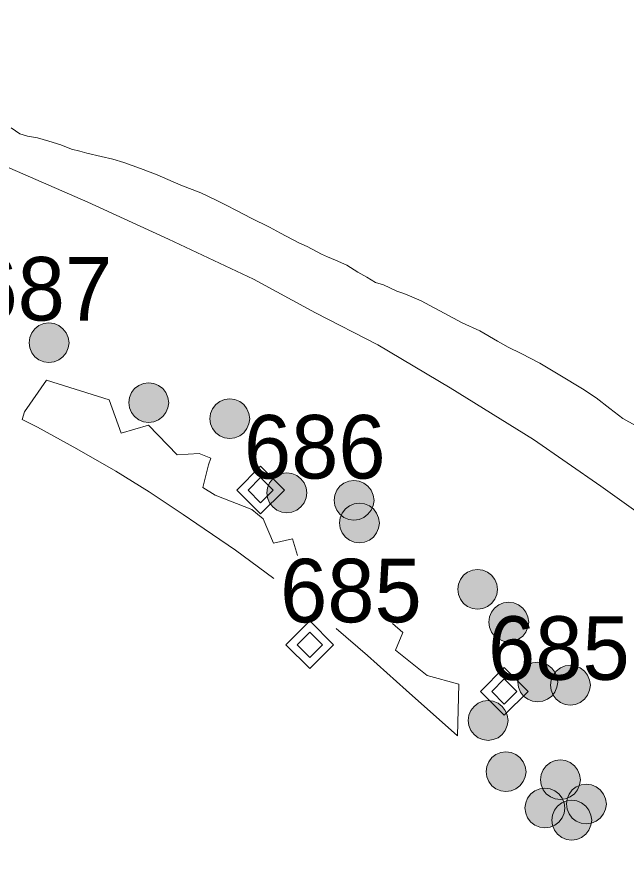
# Model space of a CAD drawing. Extents: x 3461750 to 3585707, y 5917729 to 5985917.
# Drawn here: x 3518777 to 3520696, y 5968997 to 5971646 of the extents above; entities that cross this region are included whole.
import ezdxf

# ---------------------------------------------------------------- set-up
doc = ezdxf.new("R2010")
doc.units = 0
doc.header["$LTSCALE"] = 80
for name, color, linetype, lineweight in [('12', 7, 'Continuous', 13), ('15', 7, 'Continuous', 13), ('2', 7, 'Continuous', 13), ('3', 7, 'Continuous', 13), ('6', 7, 'Continuous', 13), ('7', 7, 'Continuous', 13)]:
    doc.layers.add(name, color=color, linetype=linetype, lineweight=lineweight)

msp = doc.modelspace()

# ---------------------------------------------------------------- hatches: boundary and pattern name
at = {"layer": '3'}
for points in [[(3518941.45, 5970619.2), (3518938.52, 5970635.82), (3518932.27, 5970650.92), (3518922.32, 5970663.88), (3518909.36, 5970673.82), (3518894.27, 5970680.07), (3518878.08, 5970682.2), (3518861.88, 5970680.07), (3518846.79, 5970673.82), (3518833.83, 5970663.88), (3518823.88, 5970650.92), (3518817.63, 5970635.82), (3518815.5, 5970619.63), (3518817.63, 5970603.43), (3518823.88, 5970588.34), (3518833.83, 5970575.38), (3518846.79, 5970565.44), (3518861.88, 5970559.19), (3518878.08, 5970557.05), (3518894.27, 5970559.19), (3518909.36, 5970565.44), (3518922.32, 5970575.38), (3518932.27, 5970588.34), (3518938.52, 5970603.43)], [(3519255.41, 5970430.92), (3519252.48, 5970447.54), (3519246.23, 5970462.64), (3519236.29, 5970475.6), (3519223.33, 5970485.54), (3519208.24, 5970491.79), (3519192.04, 5970493.92), (3519175.85, 5970491.79), (3519160.75, 5970485.54), (3519147.79, 5970475.6), (3519137.85, 5970462.64), (3519131.6, 5970447.54), (3519129.47, 5970431.35), (3519131.6, 5970415.15), (3519137.85, 5970400.06), (3519147.79, 5970387.1), (3519160.75, 5970377.16), (3519175.85, 5970370.91), (3519192.04, 5970368.77), (3519208.24, 5970370.91), (3519223.33, 5970377.16), (3519236.29, 5970387.1), (3519246.23, 5970400.06), (3519252.48, 5970415.15)], [(3519510.98, 5970380.14), (3519508.05, 5970396.76), (3519501.8, 5970411.85), (3519491.85, 5970424.81), (3519478.89, 5970434.76), (3519463.8, 5970441.01), (3519447.61, 5970443.14), (3519431.41, 5970441.01), (3519416.32, 5970434.76), (3519403.36, 5970424.81), (3519393.42, 5970411.85), (3519387.16, 5970396.76), (3519385.03, 5970380.57), (3519387.16, 5970364.37), (3519393.42, 5970349.28), (3519403.36, 5970336.32), (3519416.32, 5970326.37), (3519431.41, 5970320.12), (3519447.61, 5970317.99), (3519463.8, 5970320.12), (3519478.89, 5970326.37), (3519491.85, 5970336.32), (3519501.8, 5970349.28), (3519508.05, 5970364.37)], [(3519690.72, 5970146.74), (3519687.79, 5970163.36), (3519681.54, 5970178.46), (3519671.59, 5970191.42), (3519658.63, 5970201.36), (3519643.54, 5970207.61), (3519627.34, 5970209.74), (3519611.15, 5970207.61), (3519596.06, 5970201.36), (3519583.1, 5970191.42), (3519573.15, 5970178.46), (3519566.9, 5970163.36), (3519564.77, 5970147.17), (3519566.9, 5970130.97), (3519573.15, 5970115.88), (3519583.1, 5970102.92), (3519596.06, 5970092.98), (3519611.15, 5970086.73), (3519627.34, 5970084.59), (3519643.54, 5970086.73), (3519658.63, 5970092.98), (3519671.59, 5970102.92), (3519681.54, 5970115.88), (3519687.79, 5970130.97)], [(3519901.9, 5970123.4), (3519898.97, 5970140.02), (3519892.72, 5970155.12), (3519882.77, 5970168.08), (3519869.81, 5970178.02), (3519854.72, 5970184.27), (3519838.52, 5970186.4), (3519822.33, 5970184.27), (3519807.24, 5970178.02), (3519794.28, 5970168.08), (3519784.33, 5970155.12), (3519778.08, 5970140.02), (3519775.95, 5970123.83), (3519778.08, 5970107.63), (3519784.33, 5970092.54), (3519794.28, 5970079.58), (3519807.24, 5970069.64), (3519822.33, 5970063.39), (3519838.52, 5970061.25), (3519854.72, 5970063.39), (3519869.81, 5970069.64), (3519882.77, 5970079.58), (3519892.72, 5970092.54), (3519898.97, 5970107.63)], [(3519919.33, 5970051.91), (3519916.4, 5970068.54), (3519910.15, 5970083.63), (3519900.2, 5970096.59), (3519887.24, 5970106.54), (3519872.15, 5970112.79), (3519855.96, 5970114.92), (3519839.76, 5970112.79), (3519824.67, 5970106.54), (3519811.71, 5970096.59), (3519801.77, 5970083.63), (3519795.51, 5970068.54), (3519793.38, 5970052.34), (3519795.51, 5970036.15), (3519801.77, 5970021.06), (3519811.71, 5970008.1), (3519824.67, 5969998.15), (3519839.76, 5969991.9), (3519855.96, 5969989.77), (3519872.15, 5969991.9), (3519887.24, 5969998.15), (3519900.2, 5970008.1), (3519910.15, 5970021.06), (3519916.4, 5970036.15)], [(3520291.35, 5969842.93), (3520288.42, 5969859.55), (3520282.17, 5969874.65), (3520272.23, 5969887.61), (3520259.27, 5969897.55), (3520244.17, 5969903.8), (3520227.98, 5969905.93), (3520211.78, 5969903.8), (3520196.69, 5969897.55), (3520183.73, 5969887.61), (3520173.79, 5969874.65), (3520167.54, 5969859.55), (3520165.4, 5969843.36), (3520167.54, 5969827.16), (3520173.79, 5969812.07), (3520183.73, 5969799.11), (3520196.69, 5969789.17), (3520211.78, 5969782.92), (3520227.98, 5969780.78), (3520244.17, 5969782.92), (3520259.27, 5969789.17), (3520272.23, 5969799.11), (3520282.17, 5969812.07), (3520288.42, 5969827.16)], [(3520389.5, 5969739.8), (3520386.57, 5969756.43), (3520380.31, 5969771.52), (3520370.37, 5969784.48), (3520357.41, 5969794.43), (3520342.32, 5969800.68), (3520326.12, 5969802.81), (3520309.93, 5969800.68), (3520294.84, 5969794.43), (3520281.88, 5969784.48), (3520271.93, 5969771.52), (3520265.68, 5969756.43), (3520263.55, 5969740.23), (3520265.68, 5969724.04), (3520271.93, 5969708.95), (3520281.88, 5969695.99), (3520294.84, 5969686.04), (3520309.93, 5969679.79), (3520326.12, 5969677.66), (3520342.32, 5969679.79), (3520357.41, 5969686.04), (3520370.37, 5969695.99), (3520380.31, 5969708.95), (3520386.57, 5969724.04)], [(3520480.76, 5969550.84), (3520477.83, 5969567.47), (3520471.57, 5969582.56), (3520461.63, 5969595.52), (3520448.67, 5969605.46), (3520433.58, 5969611.71), (3520417.38, 5969613.85), (3520401.19, 5969611.71), (3520386.1, 5969605.46), (3520373.14, 5969595.52), (3520363.19, 5969582.56), (3520356.94, 5969567.47), (3520354.81, 5969551.27), (3520356.94, 5969535.07), (3520363.19, 5969519.98), (3520373.14, 5969507.02), (3520386.1, 5969497.08), (3520401.19, 5969490.83), (3520417.38, 5969488.69), (3520433.58, 5969490.83), (3520448.67, 5969497.08), (3520461.63, 5969507.02), (3520471.57, 5969519.98), (3520477.83, 5969535.07)], [(3520583.59, 5969541.17), (3520580.66, 5969557.8), (3520574.41, 5969572.89), (3520564.46, 5969585.85), (3520551.5, 5969595.79), (3520536.41, 5969602.04), (3520520.22, 5969604.18), (3520504.02, 5969602.04), (3520488.93, 5969595.79), (3520475.97, 5969585.85), (3520466.02, 5969572.89), (3520459.77, 5969557.8), (3520457.64, 5969541.6), (3520459.77, 5969525.41), (3520466.02, 5969510.31), (3520475.97, 5969497.35), (3520488.93, 5969487.41), (3520504.02, 5969481.16), (3520520.22, 5969479.03), (3520536.41, 5969481.16), (3520551.5, 5969487.41), (3520564.46, 5969497.35), (3520574.41, 5969510.31), (3520580.66, 5969525.41)], [(3520324.51, 5969430.04), (3520321.58, 5969446.66), (3520315.32, 5969461.76), (3520305.38, 5969474.72), (3520292.42, 5969484.66), (3520277.33, 5969490.91), (3520261.13, 5969493.04), (3520244.94, 5969490.91), (3520229.85, 5969484.66), (3520216.89, 5969474.72), (3520206.94, 5969461.76), (3520200.69, 5969446.66), (3520198.56, 5969430.47), (3520200.69, 5969414.27), (3520206.94, 5969399.18), (3520216.89, 5969386.22), (3520229.85, 5969376.28), (3520244.94, 5969370.03), (3520261.13, 5969367.89), (3520277.33, 5969370.03), (3520292.42, 5969376.28), (3520305.38, 5969386.22), (3520315.32, 5969399.18), (3520321.58, 5969414.27)], [(3520380.61, 5969268.91), (3520377.68, 5969285.53), (3520371.43, 5969300.62), (3520361.48, 5969313.58), (3520348.52, 5969323.53), (3520333.43, 5969329.78), (3520317.24, 5969331.91), (3520301.04, 5969329.78), (3520285.95, 5969323.53), (3520272.99, 5969313.58), (3520263.04, 5969300.62), (3520256.79, 5969285.53), (3520254.66, 5969269.34), (3520256.79, 5969253.14), (3520263.04, 5969238.05), (3520272.99, 5969225.09), (3520285.95, 5969215.14), (3520301.04, 5969208.89), (3520317.24, 5969206.76), (3520333.43, 5969208.89), (3520348.52, 5969215.14), (3520361.48, 5969225.09), (3520371.43, 5969238.05), (3520377.68, 5969253.14)], [(3520552.24, 5969243.42), (3520549.31, 5969260.04), (3520543.06, 5969275.14), (3520533.11, 5969288.1), (3520520.15, 5969298.04), (3520505.06, 5969304.29), (3520488.87, 5969306.42), (3520472.67, 5969304.29), (3520457.58, 5969298.04), (3520444.62, 5969288.1), (3520434.68, 5969275.14), (3520428.42, 5969260.04), (3520426.29, 5969243.85), (3520428.42, 5969227.65), (3520434.68, 5969212.56), (3520444.62, 5969199.6), (3520457.58, 5969189.66), (3520472.67, 5969183.41), (3520488.87, 5969181.27), (3520505.06, 5969183.41), (3520520.15, 5969189.66), (3520533.11, 5969199.6), (3520543.06, 5969212.56), (3520549.31, 5969227.65)], [(3520633.78, 5969167.15), (3520630.85, 5969183.77), (3520624.6, 5969198.87), (3520614.66, 5969211.83), (3520601.7, 5969221.77), (3520586.61, 5969228.02), (3520570.41, 5969230.15), (3520554.21, 5969228.02), (3520539.12, 5969221.77), (3520526.16, 5969211.83), (3520516.22, 5969198.87), (3520509.97, 5969183.77), (3520507.83, 5969167.58), (3520509.97, 5969151.38), (3520516.22, 5969136.29), (3520526.16, 5969123.33), (3520539.12, 5969113.39), (3520554.21, 5969107.14), (3520570.41, 5969105), (3520586.61, 5969107.14), (3520601.7, 5969113.39), (3520614.66, 5969123.33), (3520624.6, 5969136.29), (3520630.85, 5969151.38)], [(3520503.36, 5969154.55), (3520500.43, 5969171.18), (3520494.18, 5969186.27), (3520484.24, 5969199.23), (3520471.28, 5969209.17), (3520456.19, 5969215.42), (3520439.99, 5969217.56), (3520423.79, 5969215.42), (3520408.7, 5969209.17), (3520395.74, 5969199.23), (3520385.8, 5969186.27), (3520379.55, 5969171.18), (3520377.41, 5969154.98), (3520379.55, 5969138.78), (3520385.8, 5969123.69), (3520395.74, 5969110.73), (3520408.7, 5969100.79), (3520423.79, 5969094.54), (3520439.99, 5969092.4), (3520456.19, 5969094.54), (3520471.28, 5969100.79), (3520484.24, 5969110.73), (3520494.18, 5969123.69), (3520500.43, 5969138.78)], [(3520587.69, 5969116.17), (3520584.76, 5969132.8), (3520578.51, 5969147.89), (3520568.56, 5969160.85), (3520555.6, 5969170.79), (3520540.51, 5969177.04), (3520524.32, 5969179.18), (3520508.12, 5969177.04), (3520493.03, 5969170.79), (3520480.07, 5969160.85), (3520470.12, 5969147.89), (3520463.87, 5969132.8), (3520461.74, 5969116.6), (3520463.87, 5969100.41), (3520470.12, 5969085.31), (3520480.07, 5969072.35), (3520493.03, 5969062.41), (3520508.12, 5969056.16), (3520524.32, 5969054.03), (3520540.51, 5969056.16), (3520555.6, 5969062.41), (3520568.56, 5969072.35), (3520578.51, 5969085.31), (3520584.76, 5969100.41)]]:
    msp.add_hatch(color=256, dxfattribs=at).paths.add_polyline_path(points)

# ---------------------------------------------------------------- linework, layer by layer
at = {"layer": '12'}
for points in [[(3519699.69, 5969743.76), (3519624.6, 5969668.67), (3519699.69, 5969593.58), (3519774.78, 5969668.67)], [(3519699.69, 5969708.36), (3519660, 5969668.67), (3519699.69, 5969628.97), (3519739.38, 5969668.67)]]:
    msp.add_lwpolyline(points, close=True, dxfattribs=at)
at = {"layer": '15'}
for points in [[(3519544.81, 5970230.86), (3519469.72, 5970155.77), (3519544.81, 5970080.68), (3519619.9, 5970155.77)], [(3519544.81, 5970195.47), (3519505.12, 5970155.77), (3519544.81, 5970116.08), (3519584.5, 5970155.77)], [(3520312.29, 5969596.98), (3520237.2, 5969521.89), (3520312.29, 5969446.8), (3520387.38, 5969521.89)], [(3520312.29, 5969561.58), (3520272.6, 5969521.89), (3520312.29, 5969482.19), (3520351.98, 5969521.89)]]:
    msp.add_lwpolyline(points, close=True, dxfattribs=at)
at = {"layer": '2'}
for p, q in [((3518801.37, 5970401.95), (3518793.46, 5970378.32)), ((3520165.14, 5969381.74), (3520003.03, 5969525.98))]:
    msp.add_line(p, q, dxfattribs=at)
for points in [[(3519660.55, 5969949.5), (3519644.82, 5970002.83), (3519584.96, 5969988.38), (3519553.03, 5970065.82), (3519516.89, 5970094.34), (3519402.15, 5970140.04), (3519362.79, 5970164.16), (3519380.42, 5970234.96), (3519388.23, 5970256.05), (3519351.03, 5970270.9), (3519282.47, 5970266.7), (3519191.55, 5970360.25), (3519105.86, 5970335.35), (3519067.92, 5970439.65), (3518870.36, 5970501.46), (3518801.37, 5970401.95)], [(3519300.34, 5970078.91), (3519194.04, 5970150.39), (3519088.53, 5970215.04), (3518966.02, 5970285.64), (3518841.94, 5970354.3), (3518793.46, 5970378.32)], [(3519586.1, 5969877.96), (3519465.53, 5969966.8), (3519343.7, 5970049.8), (3519300.34, 5970078.91)], [(3520165.14, 5969381.74), (3520169.58, 5969544.34), (3520068.9, 5969572.27), (3519969.97, 5969651.86), (3519993.07, 5969706.93), (3519959.7, 5969736.14)], [(3520003.03, 5969525.98), (3519881.35, 5969634.77), (3519782.3, 5969719.5)]]:
    msp.add_lwpolyline(points, dxfattribs=at)
at = {"layer": '3'}
for points in [[(3518941.45, 5970619.2), (3518938.52, 5970635.82), (3518932.27, 5970650.92), (3518922.32, 5970663.88), (3518909.36, 5970673.82), (3518894.27, 5970680.07), (3518878.08, 5970682.2), (3518861.88, 5970680.07), (3518846.79, 5970673.82), (3518833.83, 5970663.88), (3518823.88, 5970650.92), (3518817.63, 5970635.82), (3518815.5, 5970619.63), (3518817.63, 5970603.43), (3518823.88, 5970588.34), (3518833.83, 5970575.38), (3518846.79, 5970565.44), (3518861.88, 5970559.19), (3518878.08, 5970557.05), (3518894.27, 5970559.19), (3518909.36, 5970565.44), (3518922.32, 5970575.38), (3518932.27, 5970588.34), (3518938.52, 5970603.43)], [(3519255.41, 5970430.92), (3519252.48, 5970447.54), (3519246.23, 5970462.64), (3519236.29, 5970475.6), (3519223.33, 5970485.54), (3519208.24, 5970491.79), (3519192.04, 5970493.92), (3519175.85, 5970491.79), (3519160.75, 5970485.54), (3519147.79, 5970475.6), (3519137.85, 5970462.64), (3519131.6, 5970447.54), (3519129.47, 5970431.35), (3519131.6, 5970415.15), (3519137.85, 5970400.06), (3519147.79, 5970387.1), (3519160.75, 5970377.16), (3519175.85, 5970370.91), (3519192.04, 5970368.77), (3519208.24, 5970370.91), (3519223.33, 5970377.16), (3519236.29, 5970387.1), (3519246.23, 5970400.06), (3519252.48, 5970415.15)], [(3519510.98, 5970380.14), (3519508.05, 5970396.76), (3519501.8, 5970411.85), (3519491.85, 5970424.81), (3519478.89, 5970434.76), (3519463.8, 5970441.01), (3519447.61, 5970443.14), (3519431.41, 5970441.01), (3519416.32, 5970434.76), (3519403.36, 5970424.81), (3519393.42, 5970411.85), (3519387.16, 5970396.76), (3519385.03, 5970380.57), (3519387.16, 5970364.37), (3519393.42, 5970349.28), (3519403.36, 5970336.32), (3519416.32, 5970326.37), (3519431.41, 5970320.12), (3519447.61, 5970317.99), (3519463.8, 5970320.12), (3519478.89, 5970326.37), (3519491.85, 5970336.32), (3519501.8, 5970349.28), (3519508.05, 5970364.37)], [(3519690.72, 5970146.74), (3519687.79, 5970163.36), (3519681.54, 5970178.46), (3519671.59, 5970191.42), (3519658.63, 5970201.36), (3519643.54, 5970207.61), (3519627.34, 5970209.74), (3519611.15, 5970207.61), (3519596.06, 5970201.36), (3519583.1, 5970191.42), (3519573.15, 5970178.46), (3519566.9, 5970163.36), (3519564.77, 5970147.17), (3519566.9, 5970130.97), (3519573.15, 5970115.88), (3519583.1, 5970102.92), (3519596.06, 5970092.98), (3519611.15, 5970086.73), (3519627.34, 5970084.59), (3519643.54, 5970086.73), (3519658.63, 5970092.98), (3519671.59, 5970102.92), (3519681.54, 5970115.88), (3519687.79, 5970130.97)], [(3519901.9, 5970123.4), (3519898.97, 5970140.02), (3519892.72, 5970155.12), (3519882.77, 5970168.08), (3519869.81, 5970178.02), (3519854.72, 5970184.27), (3519838.52, 5970186.4), (3519822.33, 5970184.27), (3519807.24, 5970178.02), (3519794.28, 5970168.08), (3519784.33, 5970155.12), (3519778.08, 5970140.02), (3519775.95, 5970123.83), (3519778.08, 5970107.63), (3519784.33, 5970092.54), (3519794.28, 5970079.58), (3519807.24, 5970069.64), (3519822.33, 5970063.39), (3519838.52, 5970061.25), (3519854.72, 5970063.39), (3519869.81, 5970069.64), (3519882.77, 5970079.58), (3519892.72, 5970092.54), (3519898.97, 5970107.63)], [(3519919.33, 5970051.91), (3519916.4, 5970068.54), (3519910.15, 5970083.63), (3519900.2, 5970096.59), (3519887.24, 5970106.54), (3519872.15, 5970112.79), (3519855.96, 5970114.92), (3519839.76, 5970112.79), (3519824.67, 5970106.54), (3519811.71, 5970096.59), (3519801.77, 5970083.63), (3519795.51, 5970068.54), (3519793.38, 5970052.34), (3519795.51, 5970036.15), (3519801.77, 5970021.06), (3519811.71, 5970008.1), (3519824.67, 5969998.15), (3519839.76, 5969991.9), (3519855.96, 5969989.77), (3519872.15, 5969991.9), (3519887.24, 5969998.15), (3519900.2, 5970008.1), (3519910.15, 5970021.06), (3519916.4, 5970036.15)], [(3520291.35, 5969842.93), (3520288.42, 5969859.55), (3520282.17, 5969874.65), (3520272.23, 5969887.61), (3520259.27, 5969897.55), (3520244.17, 5969903.8), (3520227.98, 5969905.93), (3520211.78, 5969903.8), (3520196.69, 5969897.55), (3520183.73, 5969887.61), (3520173.79, 5969874.65), (3520167.54, 5969859.55), (3520165.4, 5969843.36), (3520167.54, 5969827.16), (3520173.79, 5969812.07), (3520183.73, 5969799.11), (3520196.69, 5969789.17), (3520211.78, 5969782.92), (3520227.98, 5969780.78), (3520244.17, 5969782.92), (3520259.27, 5969789.17), (3520272.23, 5969799.11), (3520282.17, 5969812.07), (3520288.42, 5969827.16)], [(3520389.5, 5969739.8), (3520386.57, 5969756.43), (3520380.31, 5969771.52), (3520370.37, 5969784.48), (3520357.41, 5969794.43), (3520342.32, 5969800.68), (3520326.12, 5969802.81), (3520309.93, 5969800.68), (3520294.84, 5969794.43), (3520281.88, 5969784.48), (3520271.93, 5969771.52), (3520265.68, 5969756.43), (3520263.55, 5969740.23), (3520265.68, 5969724.04), (3520271.93, 5969708.95), (3520281.88, 5969695.99), (3520294.84, 5969686.04), (3520309.93, 5969679.79), (3520326.12, 5969677.66), (3520342.32, 5969679.79), (3520357.41, 5969686.04), (3520370.37, 5969695.99), (3520380.31, 5969708.95), (3520386.57, 5969724.04)], [(3520480.76, 5969550.84), (3520477.83, 5969567.47), (3520471.57, 5969582.56), (3520461.63, 5969595.52), (3520448.67, 5969605.46), (3520433.58, 5969611.71), (3520417.38, 5969613.85), (3520401.19, 5969611.71), (3520386.1, 5969605.46), (3520373.14, 5969595.52), (3520363.19, 5969582.56), (3520356.94, 5969567.47), (3520354.81, 5969551.27), (3520356.94, 5969535.07), (3520363.19, 5969519.98), (3520373.14, 5969507.02), (3520386.1, 5969497.08), (3520401.19, 5969490.83), (3520417.38, 5969488.69), (3520433.58, 5969490.83), (3520448.67, 5969497.08), (3520461.63, 5969507.02), (3520471.57, 5969519.98), (3520477.83, 5969535.07)], [(3520583.59, 5969541.17), (3520580.66, 5969557.8), (3520574.41, 5969572.89), (3520564.46, 5969585.85), (3520551.5, 5969595.79), (3520536.41, 5969602.04), (3520520.22, 5969604.18), (3520504.02, 5969602.04), (3520488.93, 5969595.79), (3520475.97, 5969585.85), (3520466.02, 5969572.89), (3520459.77, 5969557.8), (3520457.64, 5969541.6), (3520459.77, 5969525.41), (3520466.02, 5969510.31), (3520475.97, 5969497.35), (3520488.93, 5969487.41), (3520504.02, 5969481.16), (3520520.22, 5969479.03), (3520536.41, 5969481.16), (3520551.5, 5969487.41), (3520564.46, 5969497.35), (3520574.41, 5969510.31), (3520580.66, 5969525.41)], [(3520324.51, 5969430.04), (3520321.58, 5969446.66), (3520315.32, 5969461.76), (3520305.38, 5969474.72), (3520292.42, 5969484.66), (3520277.33, 5969490.91), (3520261.13, 5969493.04), (3520244.94, 5969490.91), (3520229.85, 5969484.66), (3520216.89, 5969474.72), (3520206.94, 5969461.76), (3520200.69, 5969446.66), (3520198.56, 5969430.47), (3520200.69, 5969414.27), (3520206.94, 5969399.18), (3520216.89, 5969386.22), (3520229.85, 5969376.28), (3520244.94, 5969370.03), (3520261.13, 5969367.89), (3520277.33, 5969370.03), (3520292.42, 5969376.28), (3520305.38, 5969386.22), (3520315.32, 5969399.18), (3520321.58, 5969414.27)], [(3520380.61, 5969268.91), (3520377.68, 5969285.53), (3520371.43, 5969300.62), (3520361.48, 5969313.58), (3520348.52, 5969323.53), (3520333.43, 5969329.78), (3520317.24, 5969331.91), (3520301.04, 5969329.78), (3520285.95, 5969323.53), (3520272.99, 5969313.58), (3520263.04, 5969300.62), (3520256.79, 5969285.53), (3520254.66, 5969269.34), (3520256.79, 5969253.14), (3520263.04, 5969238.05), (3520272.99, 5969225.09), (3520285.95, 5969215.14), (3520301.04, 5969208.89), (3520317.24, 5969206.76), (3520333.43, 5969208.89), (3520348.52, 5969215.14), (3520361.48, 5969225.09), (3520371.43, 5969238.05), (3520377.68, 5969253.14)], [(3520552.24, 5969243.42), (3520549.31, 5969260.04), (3520543.06, 5969275.14), (3520533.11, 5969288.1), (3520520.15, 5969298.04), (3520505.06, 5969304.29), (3520488.87, 5969306.42), (3520472.67, 5969304.29), (3520457.58, 5969298.04), (3520444.62, 5969288.1), (3520434.68, 5969275.14), (3520428.42, 5969260.04), (3520426.29, 5969243.85), (3520428.42, 5969227.65), (3520434.68, 5969212.56), (3520444.62, 5969199.6), (3520457.58, 5969189.66), (3520472.67, 5969183.41), (3520488.87, 5969181.27), (3520505.06, 5969183.41), (3520520.15, 5969189.66), (3520533.11, 5969199.6), (3520543.06, 5969212.56), (3520549.31, 5969227.65)], [(3520633.78, 5969167.15), (3520630.85, 5969183.77), (3520624.6, 5969198.87), (3520614.66, 5969211.83), (3520601.7, 5969221.77), (3520586.61, 5969228.02), (3520570.41, 5969230.15), (3520554.21, 5969228.02), (3520539.12, 5969221.77), (3520526.16, 5969211.83), (3520516.22, 5969198.87), (3520509.97, 5969183.77), (3520507.83, 5969167.58), (3520509.97, 5969151.38), (3520516.22, 5969136.29), (3520526.16, 5969123.33), (3520539.12, 5969113.39), (3520554.21, 5969107.14), (3520570.41, 5969105), (3520586.61, 5969107.14), (3520601.7, 5969113.39), (3520614.66, 5969123.33), (3520624.6, 5969136.29), (3520630.85, 5969151.38)], [(3520503.36, 5969154.55), (3520500.43, 5969171.18), (3520494.18, 5969186.27), (3520484.24, 5969199.23), (3520471.28, 5969209.17), (3520456.19, 5969215.42), (3520439.99, 5969217.56), (3520423.79, 5969215.42), (3520408.7, 5969209.17), (3520395.74, 5969199.23), (3520385.8, 5969186.27), (3520379.55, 5969171.18), (3520377.41, 5969154.98), (3520379.55, 5969138.78), (3520385.8, 5969123.69), (3520395.74, 5969110.73), (3520408.7, 5969100.79), (3520423.79, 5969094.54), (3520439.99, 5969092.4), (3520456.19, 5969094.54), (3520471.28, 5969100.79), (3520484.24, 5969110.73), (3520494.18, 5969123.69), (3520500.43, 5969138.78)], [(3520587.69, 5969116.17), (3520584.76, 5969132.8), (3520578.51, 5969147.89), (3520568.56, 5969160.85), (3520555.6, 5969170.79), (3520540.51, 5969177.04), (3520524.32, 5969179.18), (3520508.12, 5969177.04), (3520493.03, 5969170.79), (3520480.07, 5969160.85), (3520470.12, 5969147.89), (3520463.87, 5969132.8), (3520461.74, 5969116.6), (3520463.87, 5969100.41), (3520470.12, 5969085.31), (3520480.07, 5969072.35), (3520493.03, 5969062.41), (3520508.12, 5969056.16), (3520524.32, 5969054.03), (3520540.51, 5969056.16), (3520555.6, 5969062.41), (3520568.56, 5969072.35), (3520578.51, 5969085.31), (3520584.76, 5969100.41)]]:
    msp.add_lwpolyline(points, close=True, dxfattribs=at)
at = {"layer": '6'}
for points in [[(3517695.53, 5971645.86), (3517728.93, 5971631.63), (3517835.9, 5971578.11), (3518001.62, 5971502.32), (3518162.94, 5971434.06), (3518340.23, 5971351.01), (3518552.91, 5971257.28), (3518755, 5971169.35), (3519000.15, 5971062.44), (3519254.97, 5970946.08), (3519521.84, 5970820.05), (3519718.05, 5970713.92), (3519913.73, 5970612.84), (3520141.41, 5970478.13), (3520403.92, 5970315.16), (3520616.77, 5970167.8), (3520826, 5970018.31), (3521044.41, 5969853.85), (3521249.21, 5969689.68), (3521446.37, 5969527.72), (3521605.97, 5969389.84), (3521777.66, 5969231.93), (3521933.88, 5969084.16), (3522032.59, 5968996.9)], [(3518759.09, 5971295.93), (3518786.94, 5971277.76), (3518810.11, 5971270.27), (3518841.68, 5971264.67), (3518877.85, 5971254.53), (3518915.1, 5971242.88), (3518949.35, 5971229.42), (3518975.51, 5971222.99), (3518997.76, 5971216.08), (3519042.67, 5971206.15), (3519079.78, 5971197.66), (3519114.07, 5971187.56), (3519166.65, 5971167.82), (3519218.67, 5971147.91), (3519252.15, 5971133.73), (3519293.96, 5971116.23), (3519356.14, 5971091.68), (3519406.6, 5971067.71), (3519433.76, 5971054.2), (3519470.88, 5971035.31), (3519514.65, 5971012.39), (3519572.84, 5970983.27), (3519607.55, 5970965.16), (3519665.34, 5970934.75), (3519691.02, 5970922.39), (3519736.06, 5970898.34), (3519755.29, 5970890.37), (3519781, 5970879.87), (3519815.92, 5970864), (3519850.95, 5970842.36), (3519878.79, 5970825.88), (3519907, 5970809.2), (3519931.83, 5970802.25), (3519974.13, 5970782.53), (3519995.41, 5970774.9), (3520020.54, 5970764.22), (3520050.3, 5970751.42), (3520078.17, 5970737.17), (3520122.44, 5970712.4), (3520179.64, 5970682.2), (3520234.87, 5970657.23), (3520290.72, 5970624.46), (3520324.09, 5970605.65), (3520365.07, 5970585.59), (3520424.48, 5970555.17), (3520487.5, 5970517.82), (3520558.98, 5970474.55), (3520602.05, 5970445.92), (3520644.49, 5970413.21), (3520685.64, 5970381.27), (3520725.08, 5970359.02)]]:
    msp.add_lwpolyline(points, dxfattribs=at)
at = {"layer": '7'}
msp.add_lwpolyline([(3517695.53, 5971645.86), (3517728.93, 5971631.63), (3517835.9, 5971578.11), (3518001.62, 5971502.32), (3518162.94, 5971434.06), (3518340.23, 5971351.01), (3518552.91, 5971257.28), (3518755, 5971169.35), (3519000.15, 5971062.44), (3519254.97, 5970946.08), (3519521.84, 5970820.05), (3519718.05, 5970713.92), (3519913.73, 5970612.84), (3520141.41, 5970478.13), (3520403.92, 5970315.16), (3520616.77, 5970167.8), (3520826, 5970018.31)], dxfattribs=at)

# ---------------------------------------------------------------- texts
at = {"layer": '12'}
msp.add_text('685', height=200, dxfattribs=at).set_placement((3519606.1, 5969739.5))
at = {"layer": '15'}
for s, p in [('687', (3518630.9, 5970689.7)), ('686', (3519492.2, 5970192.2)), ('685', (3520261, 5969558.5))]:
    msp.add_text(s, height=200, dxfattribs=at).set_placement(p)

doc.saveas('drawing.dxf')
